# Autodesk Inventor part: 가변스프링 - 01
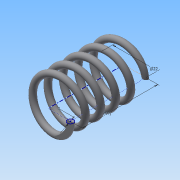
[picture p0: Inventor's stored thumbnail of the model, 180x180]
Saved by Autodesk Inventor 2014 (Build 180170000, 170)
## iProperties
Created: 2015-09
Part Number: 가변스프링 - 01
Material: 강철, 탄소
Document SubType Name: Modeling
Designer: study
Density: 7.87 g/cm^3
Appearance: 반연마
Mass: 18.8932 g
Surface Area: 32.5308 cm^2
Volume: 2.40066 cm^3
Author: study
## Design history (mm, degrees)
sketch "스케치1"
  geometry: L1 (0, 0)-(11, 0); L2 (11, 0)-(11, 37); L3 (11, 37)-(0, 37); L4 (0, 37)-(0, 0); C1 r 1.5 at (11, 0)
  constraints: 8 end point, 2 parallel, 1 centre point, 1 coincident, 1 horizontal, 1 perpendicular
  dimensions: "d0" = 22 diameter of L2 L4; "d1" = 37 distance of L1.end L2.end (derived); "d2" = 3 diameter of C1
feature "코일1" sketch "스케치1" pitch "d3" = 10; turns "d5" = 5; dims "d4" = 37 (= d1), "d6" = 0, angle "d7" = 90 deg, angle "d8" = 90 deg, "d9" = 0, "d10" = 0
node "작업 평면1"
sketch "스케치2"
  geometry: L1 (-12.5, 0)-(-9.5, 0) reference; 1 further point
  constraints: 1 horizontal alignment
extrude "돌출1" cut sketch "스케치2" stored distance "d12" = 10; taper "d13" = 0 deg
node "작업 평면2"
sketch "스케치3"
  geometry: L1 (-9.5, 0)-(-12.5, 0) reference; 1 further point
  constraints: 1 horizontal alignment
extrude "돌출2" cut sketch "스케치3" stored distance "d15" = 10; taper "d16" = 0 deg
node "솔리드1"
node "절단 모서리 투영1"
node "절단 모서리 투영2"
other parameters: "d11" = 0, "d14" = 37 (= d1)
